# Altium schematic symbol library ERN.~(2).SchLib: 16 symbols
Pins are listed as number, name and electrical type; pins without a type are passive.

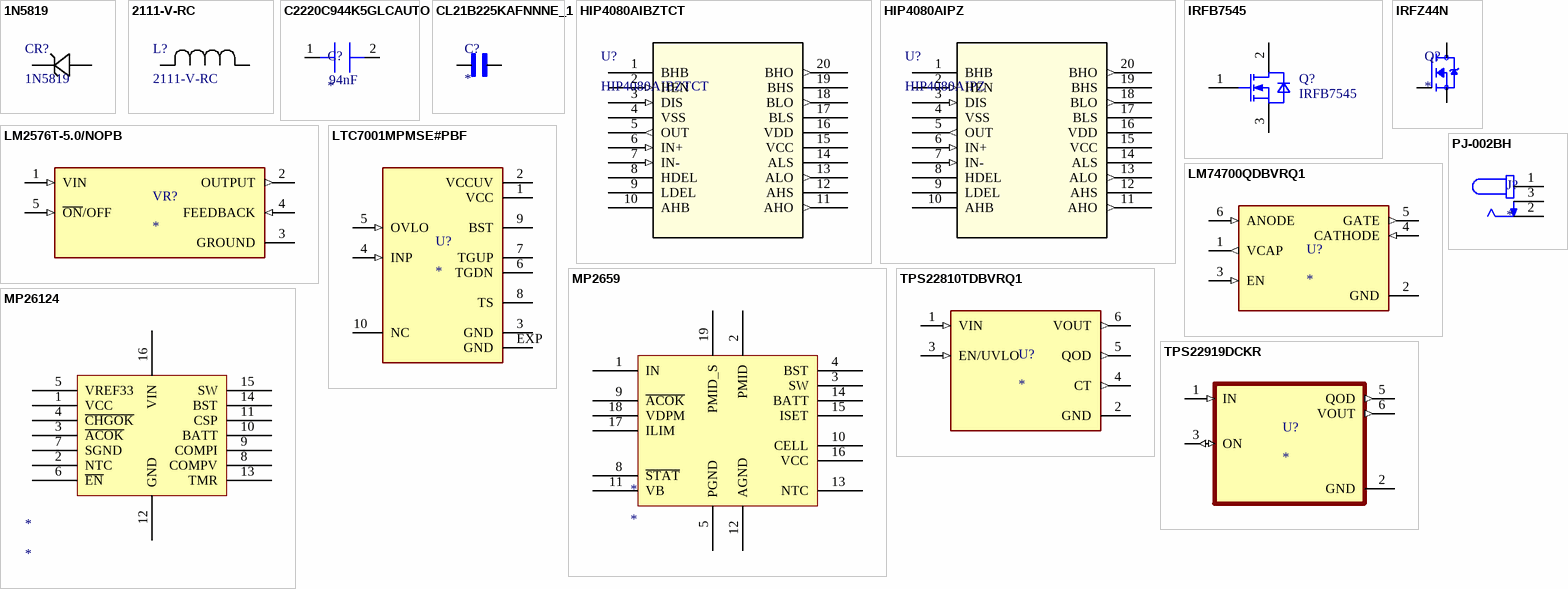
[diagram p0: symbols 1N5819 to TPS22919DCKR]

## 1N5819
designator CR?
40 V, 1 A axial Power Schottky Rectifier; Manufacturer_Name: STMicroelectronics
footprint DO-41_STM
pins: 1, 2

## 2111-V-RC
designator L?
Inductor 68uH; Manufacturer_Name: Bourns Electronics
footprint IND_21XX_27A_V
pins: 1, 2

## C2220C944K5GLCAUTO
designator C?  Capacitance: 94nF
CAP CER 0.94UF 50V C0G/NP0 2220
footprint CAPC5750X39M (Chip Capacitor, 2-Leads, Body 5.70x5.00mm, IPC Low Density)
pins: 1, 2

## CL21B225KAFNNNE_1
designator C?
2.2 ÂµF Â±10% 25V Ceramic Capacitor X7R 0805 (2012 Metric); MF: Samsung; MP: CL21B225KAFNNNE
footprint CAPC2012X135N
pins: 1, 2

## HIP4080AIBZTCT
designator U?
H Bridge Driver; Manufacturer_Name: Renesas / Intersil
footprint SOIC20_7P60X13_INR
pins: 1 BHB, 2 HEN (in), 3 DIS (in), 4 VSS (power), 5 OUT (out), 6 IN+ (in), 7 IN- (in), 8 HDEL, 9 LDEL, 10 AHB, 11 AHO (out), 12 AHS, 13 ALO (out), 14 ALS, 15 VCC (power), 16 VDD (power), 17 BLS, 18 BLO (out), 19 BHS, 20 BHO (out)

## HIP4080AIPZ
designator U?
No Description Available; Manufacturer_Name: Renesas / Intersil
footprint PDIP20_7P11X26P9_INR
pins: 1 BHB, 2 HEN (in), 3 DIS (in), 4 VSS (power), 5 OUT (out), 6 IN+ (in), 7 IN- (in), 8 HDEL, 9 LDEL, 10 AHB, 11 AHO (out), 12 AHS, 13 ALO (out), 14 ALS, 15 VCC (power), 16 VDD (power), 17 BLS, 18 BLO (out), 19 BHS, 20 BHO (out)

## IRFB7545
designator Q?
N-Channel 60V 95A; Insulated-Gate Field-Effect Transistor (IGFET), N-Channel, Enhancement, Body Diode, Pin 1 Gate, 2 Drain, 3 Source, 3 Pins; Manufacturer: Infineon Technologies
footprint IFX-PG-TO220-3-904 (TO,flange mount,2.54mm pitch;3 pin,4.45mm L X 10.66mm W X 19.15mm H body)
pins: 1 GATE, 2 DRAIN, 3 SOURCE

## IRFZ44N
designator Q?
N-Channel 55 V 49A (Tc) 94W (Tc) Through Hole TO-220AB; MP: IRFZ44N; MF: Infineon Technologies
footprint TO254P1016X419X2286-3
pins: 1 G, 2 D, 3 S

## LM2576T-5.0/NOPB
designator VR?
SIMPLE SWITCHERÂ® 40V, 3A Low Component Count Step-Down Regulator; MF: Texas Instruments; MP: LM2576T-5.0/NOPB
footprint TO170P1067X483X1651-5
pins: 1 VIN (in), 2 OUTPUT (out), 3 GROUND (power), 4 FEEDBACK (in), 5 ~{ON}/OFF (in)

## LM74700QDBVRQ1
designator U?
3.2-V to 65-V, 80-uA IQ automotive ideal diode controller; MF: Texas Instruments; MP: LM74700QDBVRQ1
footprint SOT95P280X145-6N
pins: 1 VCAP (out), 2 GND (power), 3 EN (in), 4 CATHODE (in), 5 GATE (out), 6 ANODE (in)

## LTC7001MPMSE#PBF
designator U?
Fast 150V High Side NMOS Static Switch Driver; MF: Analog Devices; MP: LTC7001MPMSE#PBF
footprint SOP50P490X110-11N
pins: 1 VCC (power), 2 VCCUV (power), 3 GND (power), 4 INP (in), 5 OVLO (in), 6 TGDN, 7 TGUP, 8 TS, 9 BST, 10 NC, EXP GND (power)

## MP2659
designator *
3S-6S Standalone Switching Charger
pins: 1 IN, 2 PMID, 3 SW, 4 BST, 5 PGND, 8 ~{STAT}, 9 ~{ACOK}, 10 CELL, 11 VB, 12 AGND, 13 NTC, 14 BATT, 15 ISET, 16 VCC, 17 ILIM, 18 VDPM, 19 PMID_S

## MP26124
designator *
24V Input, 2A, 600kHz, 4S Cell Switching Li-Ion Battery Charger
footprint QFN65P400X400X100_HS-17N (QFN, 16-Leads, Body 4.00x4.00mm, Pitch 0.65mm, Thermal Pad 2.30x2.30mm, IPC Medium Density)
pins: 1 VCC, 2 NTC, 3 ~{ACOK}, 4 ~{CHGOK}, 5 VREF33, 6 ~{EN}, 7 SGND, 8 COMPV, 9 COMPI, 10 BATT, 11 CSP, 12 GND, 13 TMR, 14 BST, 15 SW, 16 VIN

## PJ-002BH
designator J?
2.5 x 6.5 mm, 5.0 A, Horizontal, Through Hole, Dc Power Jack Connector; MF: Same Sky; MP: PJ-002BH
footprint CUI_PJ-002BH
pins: 1, 2, 3

## TPS22810TDBVRQ1
designator U?
Automotive 1-channel, 18-V, 2-A, 79-mâ„¦ load switch with adj. rise time and adj. output discharge; MF: Texas Instruments; MP: TPS22810TDBVRQ1
footprint SOT95P280X145-6N
pins: 1 VIN (in), 2 GND (power), 3 EN/UVLO (in), 4 CT (out), 5 QOD (out), 6 VOUT (out)

## TPS22919DCKR
designator U?
5.5-V, 1.5-A, 90-mÎ© load switch with adj. output discharge; MF: Texas Instruments; MP: TPS22919DCKR
footprint SOT65P210X110-6N
pins: 1 IN (in), 2 GND (power), 3 ON (io), 5 QOD (out), 6 VOUT (out)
